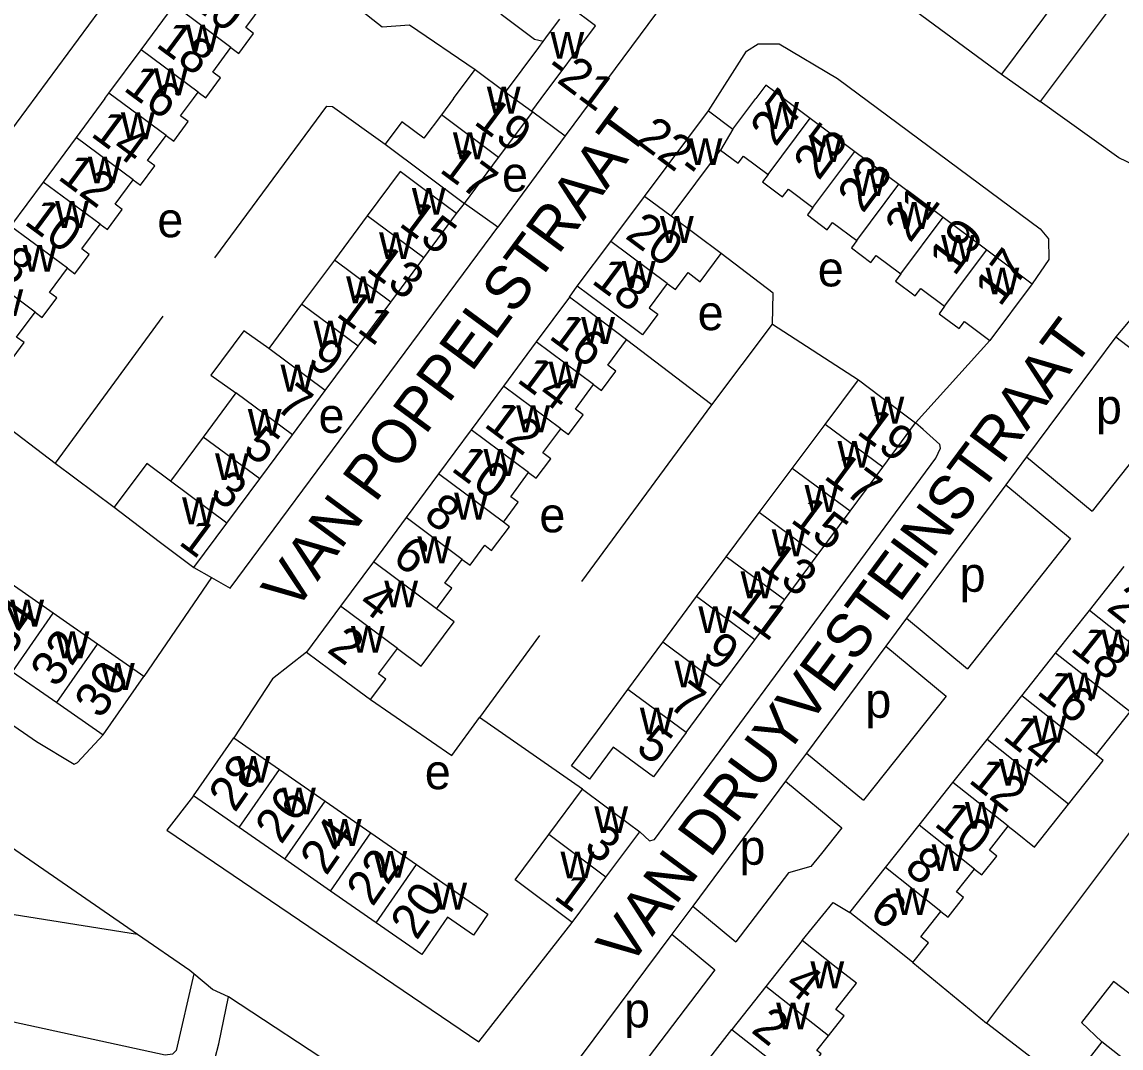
# Model space of a CAD drawing. Extents: x 159294 to 161936, y 384538 to 386517.
# Drawn here: x 160269 to 160395, y 385141.3 to 385258.8 of the extents above; entities that cross this region are included whole.
import ezdxf

# ---------------------------------------------------------------- set-up
doc = ezdxf.new("R2010")
doc.units = 0
for name, color, linetype in [('BLT_Basislijn', 7, 'Continuous'), ('BLT_Bebouwing', 7, 'Continuous'), ('BLT_Centroide', 7, 'Continuous'), ('BLT_Huisnummer', 7, 'Continuous'), ('BLT_Huisnummer_ tussenligend', 7, 'Continuous'), ('BLT_Huisnummer_reeks', 7, 'Continuous'), ('BLT_Onderverdeling_panden', 7, 'Continuous'), ('BLT_Straatnaam', 7, 'Continuous')]:
    doc.layers.add(name, color=color, linetype=linetype)

msp = doc.modelspace()

# ---------------------------------------------------------------- linework, layer by layer
at = {"layer": 'BLT_Basislijn'}
for p, q in [((160396.06, 385263.5), (160385.69, 385249.68)), ((160381.29, 385252.8), (160385.69, 385249.68)), ((160327.56, 385248.48), (160331.29, 385245.72)), ((160331.29, 385245.72), (160323.57, 385235.29)), ((160318.82, 385236.82), (160319.74, 385238)), ((160323.57, 385235.29), (160319.74, 385238)), ((160331.76, 385227.26), (160332.64, 385228.53)), ((160348.09, 385214.93), (160355.05, 385224.16)), ((160355.05, 385224.16), (160364.9, 385217.78)), ((160394.38, 385222.72), (160384.15, 385208.97)), ((160348.09, 385214.93), (160338.32, 385222.39)), ((160371.43, 385212.87), (160379.95, 385222.3)), ((160261.35, 385216.97), (160272.84, 385208.26)), ((160333.2, 385194.71), (160348.09, 385214.93)), ((160384.15, 385208.97), (160381.76, 385205.76)), ((160384.15, 385208.97), (160391.68, 385202.75)), ((160272.84, 385208.26), (160279.61, 385203.19)), ((160381.76, 385205.76), (160370.41, 385190.49)), ((160381.76, 385205.76), (160389.19, 385199.61)), ((160389.19, 385199.61), (160377.4, 385184.71)), ((160288.74, 385196.31), (160290.76, 385195.17)), ((160290.76, 385195.17), (160283.01, 385183.81)), ((160370.41, 385190.49), (160368.02, 385187.28)), ((160370.41, 385190.49), (160377.4, 385184.71)), ((160328.33, 385188.5), (160321.46, 385179.13)), ((160368.02, 385187.28), (160358.93, 385175.05)), ((160368.02, 385187.28), (160374.92, 385181.57)), ((160374.92, 385181.57), (160365.47, 385169.64)), ((160333.27, 385170.91), (160321.46, 385179.13)), ((160358.93, 385175.05), (160356.53, 385171.84)), ((160358.93, 385175.05), (160365.47, 385169.64)), ((160356.53, 385171.84), (160345.89, 385157.53)), ((160356.53, 385171.84), (160362.99, 385166.5)), ((160282.26, 385154.27), (160246.99, 385159.9)), ((160345.89, 385157.53), (160343.5, 385154.31)), ((160345.89, 385157.53), (160350.84, 385153.43)), ((160343.5, 385154.31), (160348.42, 385150.24)), ((160371.11, 385151.08), (160379.55, 385144.11)), ((160348.42, 385150.24), (160335.22, 385132.89)), ((160292.71, 385147.14), (160290.85, 385147.97)), ((160332.76, 385120.87), (160292.71, 385147.14)), ((160339.95, 385130.01), (160350.38, 385143.39)), ((160388.9, 385136.99), (160379.55, 385144.11))]:
    msp.add_line(p, q, dxfattribs=at)
for points in [[(160318.25, 385321.65), (160317.51, 385320.62), (160309.44, 385308.71), (160309.63, 385306.25), (160311.09, 385304.48), (160381.29, 385252.8)], [(160293.52, 385296.36), (160295.34, 385298.21), (160298.32, 385298.06), (160308.17, 385291.78), (160343.24, 385265.57), (160343.72, 385264.93), (160343.62, 385262.39), (160331.29, 385245.72)], [(160246.61, 385227.59), (160250.63, 385224.48), (160251.77, 385224.73), (160300.37, 385290.51), (160300.21, 385291.53), (160293.52, 385296.36)], [(160388.51, 385269.53), (160391.56, 385267.43), (160391.02, 385265.89), (160381.29, 385252.8)], [(160300.46, 385265.99), (160310.31, 385258.22), (160313.43, 385258.45), (160320.96, 385253.32)], [(160347.71, 385248.58), (160352.05, 385255.41), (160353.4, 385256.27), (160355.79, 385256.27), (160362.48, 385252.3), (160385.72, 385235.1), (160386.67, 385233.92), (160386.71, 385231.56), (160384.78, 385228.79)], [(160407.57, 385254.81), (160407.27, 385254.39), (160402.18, 385247.33), (160398.15, 385242.51), (160396.49, 385242.37), (160394.74, 385243.23), (160385.69, 385249.68)], [(160291.14, 385231.76), (160303.95, 385249.14), (160304.61, 385249.09), (160310.65, 385244.79)], [(160290.76, 385195.17), (160292.89, 385193.92), (160322.91, 385234.4), (160323.57, 385235.29)], [(160355.05, 385224.16), (160355.12, 385227.71), (160349.15, 385232.24)], [(160285.18, 385225.1), (160272.84, 385208.26)], [(160398.89, 385128.64), (160437.18, 385177.41), (160438.19, 385178.53), (160441.06, 385178.85), (160444.95, 385183.7), (160445.51, 385186.23), (160445.51, 385187.76), (160444.86, 385189.19), (160442.25, 385191.83), (160401.73, 385224.42), (160399.36, 385225.69), (160397.22, 385225.55), (160396.4, 385225.13), (160394.38, 385222.72)], [(160394.38, 385222.72), (160401.68, 385217.14), (160402.11, 385216.74), (160402.16, 385215.99), (160391.68, 385202.75)], [(160339.82, 385166.02), (160340.95, 385165), (160341.52, 385165.16), (160373.74, 385208.83), (160374.28, 385209.95), (160374.2, 385210.38), (160372.31, 385212.1), (160371.43, 385212.87)], [(160237.71, 385199.14), (160270.68, 385176.39), (160275, 385173.79), (160275.38, 385173.95), (160278.34, 385177.12)], [(160301.65, 385186.62), (160297.73, 385183.55), (160293.32, 385176.81)], [(160308.96, 385181.18), (160318.28, 385174.78), (160321.46, 385179.13)], [(160409.45, 385169.03), (160402.61, 385174.82), (160379.55, 385144.11)], [(160282.26, 385154.27), (160255.32, 385172.84)], [(160288.69, 385170.15), (160285.63, 385166.21), (160321.39, 385141.98), (160332.08, 385155.65)], [(160362.99, 385166.5), (160360.64, 385163.53), (160359.41, 385162.07), (160356.87, 385161.34), (160350.84, 385153.43)], [(160288.71, 385149.76), (160286.68, 385140.97), (160286.27, 385140.56), (160285.43, 385140.45), (160249.76, 385148.2), (160246.05, 385158.44)], [(160358.43, 385153.59), (160362, 385157.94), (160363.9, 385156.8)], [(160288.71, 385149.76), (160288.25, 385150.14), (160282.26, 385154.27)], [(160343.5, 385154.31), (160331.56, 385138.26), (160331.24, 385135.72), (160332.45, 385134.66), (160335.22, 385132.89)], [(160290.85, 385147.97), (160288.71, 385149.76)], [(160291.18, 385140.14), (160291.58, 385141.74), (160292.71, 385147.14)]]:
    msp.add_lwpolyline(points, dxfattribs=at)
at = {"layer": 'BLT_Bebouwing'}
for p, q in [((160282.68, 385255.6), (160286.45, 385260.68)), ((160279, 385250.63), (160282.68, 385255.6)), ((160318.48, 385250), (160320.96, 385253.32)), ((160320.96, 385253.32), (160324.44, 385250.72)), ((160278.53, 385250), (160279, 385250.63)), ((160288.67, 385250), (160289.22, 385250.75)), ((160278.53, 385250), (160275.23, 385245.55)), ((160318.48, 385250), (160317.09, 385248.14)), ((160327.44, 385248.57), (160328.51, 385250)), ((160350.49, 385246.5), (160353.11, 385250)), ((160356.35, 385250), (160359.35, 385247.77)), ((160323.65, 385243.24), (160327.56, 385248.48)), ((160327.56, 385248.48), (160327.44, 385248.57)), ((160340.36, 385238.8), (160347.71, 385248.58)), ((160347.71, 385248.58), (160350.49, 385246.5)), ((160359.35, 385247.77), (160364.46, 385243.95)), ((160275.23, 385245.55), (160271.45, 385240.44)), ((160310.65, 385244.79), (160319.74, 385238)), ((160343.42, 385236.52), (160349.07, 385244.1)), ((160364.46, 385243.95), (160369.5, 385240.19)), ((160319.74, 385238), (160323.65, 385243.24)), ((160271.45, 385240.44), (160267.71, 385235.4)), ((160369.5, 385240.19), (160374.58, 385236.4)), ((160336.49, 385233.65), (160340.36, 385238.8)), ((160308.59, 385236.57), (160304.83, 385231.5)), ((160315.06, 385231.76), (160318.82, 385236.82)), ((160349.15, 385232.24), (160343.42, 385236.52)), ((160374.58, 385236.4), (160379.58, 385232.67)), ((160332.64, 385228.53), (160336.49, 385233.65)), ((160379.58, 385232.67), (160384.78, 385228.79)), ((160304.83, 385231.5), (160301.07, 385226.44)), ((160311.3, 385226.69), (160315.06, 385231.76)), ((160384.78, 385228.79), (160379.95, 385222.3)), ((160301.07, 385226.44), (160297.31, 385221.37)), ((160307.54, 385221.63), (160311.3, 385226.69)), ((160331.76, 385227.26), (160327.96, 385222.13)), ((160303.78, 385216.57), (160307.54, 385221.63)), ((160327.96, 385222.13), (160324.2, 385217.06)), ((160361.08, 385212.69), (160364.9, 385217.78)), ((160293.55, 385216.31), (160289.79, 385211.24)), ((160300.02, 385211.5), (160303.78, 385216.57)), ((160324.2, 385217.06), (160320.5, 385212.06)), ((160357.3, 385207.64), (160361.08, 385212.69)), ((160367.67, 385207.8), (160371.43, 385212.87)), ((160289.79, 385211.24), (160286.03, 385206.18)), ((160296.27, 385206.44), (160300.02, 385211.5)), ((160320.5, 385212.06), (160316.75, 385207.01)), ((160353.52, 385202.59), (160357.3, 385207.64)), ((160363.92, 385202.74), (160367.67, 385207.8)), ((160292.51, 385201.37), (160296.27, 385206.44)), ((160316.75, 385207.01), (160313.05, 385202.01)), ((160349.74, 385197.54), (160353.52, 385202.59)), ((160360.16, 385197.67), (160363.92, 385202.74)), ((160288.74, 385196.31), (160292.51, 385201.37)), ((160313.05, 385202.01), (160309.31, 385196.95)), ((160346.33, 385192.99), (160349.74, 385197.54)), ((160356.4, 385192.6), (160360.16, 385197.67)), ((160309.31, 385196.95), (160305.53, 385191.86)), ((160391.36, 385191.39), (160395.35, 385196.42)), ((160272.62, 385191.06), (160267.42, 385194.69)), ((160353.02, 385188.03), (160356.4, 385192.6)), ((160277.7, 385187.52), (160272.62, 385191.06)), ((160305.53, 385191.86), (160301.65, 385186.62)), ((160387.47, 385186.49), (160391.36, 385191.39)), ((160283.01, 385183.81), (160277.7, 385187.52)), ((160338.46, 385182.34), (160342.46, 385187.74)), ((160349.13, 385182.79), (160353.02, 385188.03)), ((160383.59, 385181.6), (160387.47, 385186.49)), ((160267.95, 385184.37), (160273.03, 385180.83)), ((160278.34, 385177.12), (160283.01, 385183.81)), ((160345.13, 385177.4), (160349.13, 385182.79)), ((160379.62, 385176.6), (160383.59, 385181.6)), ((160273.03, 385180.83), (160278.34, 385177.12)), ((160288.69, 385170.15), (160293.32, 385176.81)), ((160293.32, 385176.81), (160298.55, 385173.18)), ((160375.72, 385171.69), (160379.62, 385176.6)), ((160298.55, 385173.18), (160303.78, 385169.55)), ((160329.4, 385165.72), (160333.27, 385170.91)), ((160371.83, 385166.79), (160375.72, 385171.69)), ((160293.92, 385166.52), (160288.69, 385170.15)), ((160303.78, 385169.55), (160309.01, 385165.92)), ((160299.15, 385162.89), (160293.92, 385166.52)), ((160309.01, 385165.92), (160314.24, 385162.28)), ((160335.95, 385160.83), (160339.82, 385166.02)), ((160367.99, 385161.95), (160371.83, 385166.79)), ((160304.38, 385159.25), (160299.15, 385162.89)), ((160332.08, 385155.65), (160335.95, 385160.83)), ((160363.9, 385156.8), (160367.99, 385161.95)), ((160309.62, 385155.62), (160304.38, 385159.25)), ((160358.43, 385153.59), (160354.27, 385148.32)), ((160354.27, 385148.32), (160350.38, 385143.39)), ((160392.79, 385141.97), (160388.9, 385136.99))]:
    msp.add_line(p, q, dxfattribs=at)
for points in [[(160328.76, 385256.52), (160327.75, 385256.76), (160323.94, 385259.61), (160323.67, 385260.26), (160324.93, 385261.94), (160325.59, 385262.83)], [(160292.98, 385255.84), (160293.87, 385255.18), (160295.56, 385257.47), (160294.67, 385258.13), (160296.67, 385260.82)], [(160328.51, 385250), (160334.74, 385258.34), (160331.88, 385260.47)], [(160324.44, 385250.72), (160328.26, 385255.84), (160328.76, 385256.52)], [(160289.22, 385250.75), (160290.1, 385250.1), (160291.78, 385252.36), (160290.89, 385253.02), (160292.98, 385255.84)], [(160356.35, 385250), (160354.27, 385251.55), (160353.11, 385250)], [(160285.55, 385245.78), (160286.42, 385245.13), (160288.09, 385247.38), (160287.21, 385248.03), (160288.67, 385250)], [(160317.09, 385248.14), (160315.08, 385245.45), (160312.56, 385247.34), (160310.65, 385244.79)], [(160281.77, 385240.7), (160282.6, 385240.09), (160284.25, 385242.31), (160283.43, 385242.91), (160285.55, 385245.78)], [(160349.07, 385244.1), (160351.1, 385242.59), (160351.71, 385243.42), (160354.53, 385241.31)], [(160318.82, 385236.82), (160314.81, 385239.8), (160312.35, 385241.63), (160308.59, 385236.57)], [(160277.97, 385235.61), (160278.81, 385234.99), (160280.52, 385237.29), (160279.7, 385237.9), (160281.77, 385240.7)], [(160354.53, 385241.31), (160353.9, 385240.47), (160356.19, 385238.76), (160356.85, 385239.64), (160359.67, 385237.54)], [(160359.67, 385237.54), (160359.03, 385236.68), (160361.31, 385234.97), (160361.92, 385235.8), (160364.69, 385233.73)], [(160274.24, 385230.56), (160275.08, 385229.94), (160276.72, 385232.16), (160275.88, 385232.79), (160277.97, 385235.61)], [(160364.69, 385233.73), (160364.07, 385232.9), (160366.31, 385231.23), (160366.91, 385232.03), (160369.75, 385229.92)], [(160342.98, 385228.81), (160343.91, 385228.12), (160345.36, 385230.07), (160346.75, 385229.03), (160349.15, 385232.24)], [(160270.52, 385225.55), (160271.36, 385224.93), (160273.02, 385227.18), (160272.19, 385227.79), (160274.24, 385230.56)], [(160342.98, 385228.81), (160340.91, 385226.04), (160341.89, 385225.31), (160340.12, 385222.95), (160336.65, 385225.54), (160332.64, 385228.53)], [(160369.75, 385229.92), (160369.13, 385229.1), (160371.4, 385227.41), (160372.03, 385228.25), (160374.76, 385226.21)], [(160338.32, 385222.39), (160335.78, 385224.28), (160331.76, 385227.26)], [(160260.2, 385225.25), (160264.21, 385222.28), (160267.58, 385219.78), (160269.26, 385222.06), (160268.4, 385222.69), (160270.52, 385225.55)], [(160374.76, 385226.21), (160374.13, 385225.36), (160376.43, 385223.65), (160377.04, 385224.47), (160379.95, 385222.3)], [(160297.31, 385221.37), (160294.44, 385223.41), (160290.68, 385218.34), (160293.55, 385216.31)], [(160334.54, 385217.25), (160335.43, 385216.58), (160337.08, 385218.8), (160336.17, 385219.48), (160338.32, 385222.39)], [(160364.9, 385217.78), (160367.43, 385215.87), (160371.43, 385212.87)], [(160330.77, 385212.18), (160331.65, 385211.52), (160333.33, 385213.79), (160332.45, 385214.44), (160334.54, 385217.25)], [(160327.08, 385207.17), (160327.96, 385206.52), (160329.63, 385208.76), (160328.72, 385209.43), (160330.77, 385212.18)], [(160286.03, 385206.18), (160283.33, 385208.22), (160279.61, 385203.19)], [(160324.19, 385201.48), (160325.89, 385203.77), (160325.03, 385204.41), (160327.08, 385207.17)], [(160279.61, 385203.19), (160284.73, 385199.29), (160288.74, 385196.31)], [(160319.49, 385197.22), (160320.38, 385196.56), (160322.07, 385198.84), (160322.84, 385198.25), (160324.9, 385200.96), (160324.19, 385201.48)], [(160316.54, 385191.58), (160318.28, 385193.92), (160317.48, 385194.51), (160319.49, 385197.22)], [(160342.46, 385187.74), (160346.33, 385192.99)], [(160312.05, 385187.02), (160314.79, 385184.99), (160318.57, 385190.07), (160316.54, 385191.58)], [(160301.65, 385186.62), (160305.66, 385183.64), (160308.96, 385181.18)], [(160308.96, 385181.18), (160310.71, 385183.53), (160309.9, 385184.13), (160312.05, 385187.02)], [(160345.13, 385177.4), (160341.38, 385172.33), (160336.78, 385175.73), (160334.07, 385172.06), (160332, 385173.59), (160334.97, 385177.61), (160338.46, 385182.34)], [(160392.12, 385174.83), (160396.03, 385179.77)], [(160388.94, 385169.19), (160392.91, 385174.2), (160392.12, 385174.83)], [(160333.27, 385170.91), (160335.81, 385169.01), (160339.82, 385166.02)], [(160382.06, 385166.66), (160382.88, 385166.01), (160385.05, 385164.29), (160388.94, 385169.19)], [(160378.18, 385161.75), (160379.01, 385161.09), (160380.73, 385163.26), (160379.89, 385163.93), (160382.06, 385166.66)], [(160332.08, 385155.65), (160325.53, 385160.54), (160328.52, 385164.54), (160329.4, 385165.72)], [(160314.24, 385162.28), (160322.43, 385156.6), (160320.77, 385154.21), (160317.81, 385156.26), (160314.85, 385151.99), (160309.62, 385155.62)], [(160374.32, 385156.92), (160375.15, 385156.27), (160376.92, 385158.49), (160376.11, 385159.14), (160378.18, 385161.75)], [(160371.11, 385151.08), (160367.82, 385153.69), (160363.9, 385156.8)], [(160371.11, 385151.08), (160372.9, 385153.33), (160372.02, 385154.02), (160374.32, 385156.92)], [(160361.45, 385142.66), (160362.99, 385144.63), (160363.25, 385144.95), (160362.31, 385145.69), (160364.66, 385148.68), (160362.35, 385150.5), (160358.43, 385153.59)], [(160396.67, 385146.95), (160394.1, 385148.9), (160390.45, 385144.21), (160392.79, 385141.97)], [(160350.38, 385143.39), (160356.6, 385138.49), (160358.06, 385137.34), (160360.63, 385140.6), (160360.13, 385140.99), (160361.45, 385142.66)]]:
    msp.add_lwpolyline(points, dxfattribs=at)
at = {"layer": 'BLT_Onderverdeling_panden'}
for p, q in [((160292.98, 385255.84), (160286.45, 385260.68)), ((160289.22, 385250.75), (160282.68, 385255.6)), ((160285.55, 385245.78), (160279, 385250.63)), ((160324.44, 385250.72), (160327.44, 385248.57)), ((160323.65, 385243.24), (160317.09, 385248.14)), ((160354.53, 385241.31), (160359.35, 385247.77)), ((160350.49, 385246.5), (160349.07, 385244.1)), ((160281.77, 385240.7), (160275.23, 385245.55)), ((160359.67, 385237.54), (160364.46, 385243.95)), ((160277.97, 385235.61), (160271.45, 385240.44)), ((160364.69, 385233.73), (160369.5, 385240.19)), ((160343.42, 385236.52), (160340.36, 385238.8)), ((160315.06, 385231.76), (160308.59, 385236.57)), ((160369.75, 385229.92), (160374.58, 385236.4)), ((160274.24, 385230.56), (160267.71, 385235.4)), ((160342.98, 385228.81), (160336.49, 385233.65)), ((160374.76, 385226.21), (160379.58, 385232.67)), ((160311.3, 385226.69), (160304.83, 385231.5)), ((160270.52, 385225.55), (160264, 385230.38)), ((160307.54, 385221.63), (160301.07, 385226.44)), ((160303.78, 385216.57), (160297.31, 385221.37)), ((160334.54, 385217.25), (160327.96, 385222.13)), ((160300.02, 385211.5), (160293.55, 385216.31)), ((160330.77, 385212.18), (160324.2, 385217.06)), ((160367.67, 385207.8), (160361.08, 385212.69)), ((160296.27, 385206.44), (160289.79, 385211.24)), ((160327.08, 385207.17), (160320.5, 385212.06)), ((160363.92, 385202.74), (160357.3, 385207.64)), ((160292.51, 385201.37), (160286.03, 385206.18)), ((160324.19, 385201.48), (160316.75, 385207.01)), ((160360.16, 385197.67), (160353.52, 385202.59)), ((160319.49, 385197.22), (160313.05, 385202.01)), ((160356.4, 385192.6), (160349.74, 385197.54)), ((160316.54, 385191.58), (160309.31, 385196.95)), ((160353.02, 385188.03), (160346.33, 385192.99)), ((160267.95, 385184.37), (160272.62, 385191.06)), ((160312.05, 385187.02), (160305.53, 385191.86)), ((160398.51, 385185.71), (160391.36, 385191.39)), ((160273.03, 385180.83), (160277.7, 385187.52)), ((160349.13, 385182.79), (160342.46, 385187.74)), ((160396.03, 385179.77), (160387.47, 385186.49)), ((160345.13, 385177.4), (160338.46, 385182.34)), ((160392.12, 385174.83), (160383.59, 385181.6)), ((160388.94, 385169.19), (160379.62, 385176.6)), ((160293.92, 385166.52), (160298.55, 385173.18)), ((160382.06, 385166.66), (160375.72, 385171.69)), ((160299.15, 385162.89), (160303.78, 385169.55)), ((160304.38, 385159.25), (160309.01, 385165.92)), ((160378.18, 385161.75), (160371.83, 385166.79)), ((160335.95, 385160.83), (160329.4, 385165.72)), ((160309.62, 385155.62), (160314.24, 385162.28)), ((160374.32, 385156.92), (160367.99, 385161.95)), ((160361.45, 385142.66), (160354.27, 385148.32)), ((160399.3, 385136.89), (160392.79, 385141.97))]:
    msp.add_line(p, q, dxfattribs=at)
msp.add_lwpolyline([(160328.76, 385256.52), (160329.37, 385257.38), (160330.65, 385259.09)], dxfattribs=at)

# ---------------------------------------------------------------- texts
at = {"layer": 'BLT_Centroide'}
for s, p in [('w', (160287.8, 385255.38)), ('w', (160329.59, 385254.56)), ('w', (160284.15, 385250.38)), ('w', (160322.3, 385248.28)), ('w', (160354.2, 385246.52)), ('w', (160280.36, 385245.34)), ('w', (160318.41, 385243.06)), ('w', (160345.42, 385242.38)), ('w', (160359.19, 385242.72)), ('w', (160276.57, 385240.28)), ('e', (160324.04, 385239.35)), ('w', (160364.27, 385238.86)), ('w', (160313.71, 385236.69)), ('w', (160272.83, 385235.19)), ('w', (160369.33, 385235.08)), ('e', (160284.54, 385234.12)), ('w', (160342.14, 385233.47)), ('w', (160309.95, 385231.62)), ('w', (160374.36, 385231.31)), ('w', (160269.12, 385230.16)), ('w', (160337.77, 385228.31)), ('e', (160360.22, 385228.49)), ('w', (160379.45, 385227.58)), ('w', (160306.18, 385226.56)), ('w', (160265.3, 385225.09)), ('e', (160346.46, 385223.48)), ('w', (160302.43, 385221.5)), ('w', (160333.11, 385221.91)), ('w', (160298.66, 385216.44)), ('w', (160329.38, 385216.81)), ('w', (160366.27, 385212.78)), ('p', (160392.1, 385212.75)), ('w', (160294.91, 385211.38)), ('e', (160303.01, 385211.72)), ('w', (160325.67, 385211.78)), ('w', (160362.48, 385207.72)), ('w', (160291.15, 385206.31)), ('w', (160321.92, 385206.78)), ('w', (160358.71, 385202.66)), ('w', (160287.38, 385201.25)), ('w', (160318.56, 385201.78)), ('e', (160328.32, 385200.33)), ('w', (160314.34, 385196.78)), ('w', (160354.95, 385197.59)), ('p', (160376.48, 385193.52)), ('w', (160351.38, 385192.78)), ('w', (160310.55, 385191.72)), ('w', (160267.69, 385189.53)), ('w', (160346.54, 385188.78)), ('w', (160272.88, 385185.91)), ('w', (160306.73, 385186.53)), ('w', (160392.71, 385186.09)), ('w', (160278.08, 385182.28)), ('w', (160343.8, 385182.56)), ('w', (160388.85, 385181.19)), ('p', (160365.67, 385179.09)), ('w', (160339.83, 385177.19)), ('w', (160384.86, 385176.25)), ('w', (160293.62, 385171.66)), ('e', (160315.19, 385170.91)), ('w', (160380.98, 385171.31)), ('w', (160298.84, 385168.03)), ('w', (160334.61, 385165.88)), ('w', (160377.09, 385166.38)), ('w', (160304.08, 385164.41)), ('p', (160351.25, 385162.26)), ('w', (160373.26, 385161.53)), ('w', (160309.31, 385160.78)), ('w', (160330.74, 385160.69)), ('w', (160316.16, 385157.12)), ('w', (160369.12, 385156.5)), ('w', (160359.38, 385148.12)), ('p', (160338.03, 385143.63)), ('w', (160355.45, 385143.41))]:
    msp.add_text(s, height=4, dxfattribs=at).set_placement(p)
at = {"layer": 'BLT_Huisnummer'}
for s, rotation, p in [('18', 323.4739, (160284.25, 385256.02)), ('27', 53.2776, (160355.4, 385244.36)), ('14', 323.4739, (160276.78, 385245.79)), ('17', 323.4166, (160316.74, 385241.68)), ('21', 53.2761, (160370.81, 385233.37)), ('10', 323.4739, (160269.15, 385235.71)), ('15', 323.4166, (160312.09, 385235.5)), ('20', 323.3822, (160338.02, 385234.1)), ('17', 53.269, (160381.11, 385226.05)), ('18', 323.3822, (160334.16, 385228.95)), ('16', 323.3822, (160329.28, 385222.6)), ('9', 323.4166, (160301.57, 385219.69)), ('19', 323.4514, (160364.55, 385211.7)), ('5', 323.4166, (160294.21, 385209.61)), ('10', 323.3822, (160318.08, 385207.47)), ('1', 323.4166, (160286.85, 385199.03)), ('6', 323.3822, (160311.31, 385197.04)), ('13', 323.4477, (160353.38, 385196.35)), ('20', 321.5599, (160393.18, 385191.52)), ('34', 55.0885, (160267.68, 385185.95)), ('2', 323.3822, (160303.85, 385186.71)), ('9', 323.4514, (160346.82, 385186.04)), ('30', 55.0908, (160278.05, 385178.84)), ('14', 321.5621, (160381.27, 385176.76)), ('5', 323.5248, (160339.23, 385175.33)), ('28', 55.2244, (160293.43, 385168.13)), ('10', 321.5609, (160373.43, 385166.81)), ('24', 55.2302, (160303.9, 385160.9)), ('3', 323.2661, (160333.28, 385164.03)), ('1', 323.2605, (160329.83, 385158.46)), ('20', 55.2247, (160314.26, 385153.5)), ('6', 321.5639, (160365.97, 385156.53)), ('4', 321.7632, (160356.27, 385148.22)), ('2', 321.7574, (160352.46, 385143.16))]:
    msp.add_text(s, height=4, rotation=rotation, dxfattribs=at).set_placement(p)
at = {"layer": 'BLT_Huisnummer_ tussenligend'}
for s, rotation, p in [('20', 323.4739, (160287.85, 385260.99)), ('16', 323.4739, (160280.53, 385251.02)), ('19', 323.4166, (160320.67, 385247.17)), ('25', 53.2761, (160360.34, 385240.5)), ('12', 323.4739, (160273, 385240.85)), ('23', 53.2761, (160365.4, 385236.76)), ('19', 53.269, (160375.89, 385229.55)), ('8', 323.4739, (160265.96, 385230.25)), ('13', 323.4166, (160308.34, 385230.36)), ('11', 323.4166, (160304.9, 385225.18)), ('14', 323.3822, (160325.61, 385217.63)), ('7', 323.4166, (160297.94, 385214.5)), ('12', 323.3822, (160321.84, 385212.52)), ('17', 323.4477, (160360.78, 385206.57)), ('3', 323.4166, (160290.42, 385204.53)), ('8', 323.3822, (160314.9, 385201.92)), ('15', 323.4477, (160356.96, 385201.59)), ('4', 323.3822, (160307.41, 385191.86)), ('11', 323.4514, (160350.07, 385191.36)), ('32', 55.0908, (160273, 385182.42)), ('18', 321.5621, (160389.04, 385186.88)), ('16', 321.5621, (160385.19, 385181.91)), ('7', 323.5248, (160342.97, 385180.4)), ('12', 321.5609, (160377.37, 385171.78)), ('26', 55.2302, (160298.75, 385164.48)), ('22', 55.2247, (160309.21, 385157.35)), ('8', 321.5639, (160369.99, 385161.59))]:
    msp.add_text(s, height=4, rotation=rotation, dxfattribs=at).set_placement(p)
at = {"layer": 'BLT_Huisnummer_reeks'}
for s, rotation, p in [('-21', 323.2392, (160328.76, 385253.02)), ('22-', 323.2711, (160339.22, 385245.05))]:
    msp.add_text(s, height=4, rotation=rotation, dxfattribs=at).set_placement(p)
at = {"layer": 'BLT_Straatnaam'}
for s, height, rotation, p in [('THOMAS VINCIDORSTRAAT', 5, 55.5464, (160238.38, 385218.06)), ('VAN POPPELSTRAAT', 5, 53.5608, (160300.24, 385191.05)), ('VAN DRUYVESTEINSTRAAT', 4.9999, 53.4353, (160338.59, 385150.36))]:
    msp.add_text(s, height=height, rotation=rotation, dxfattribs=at).set_placement(p)

doc.saveas('drawing.dxf')
